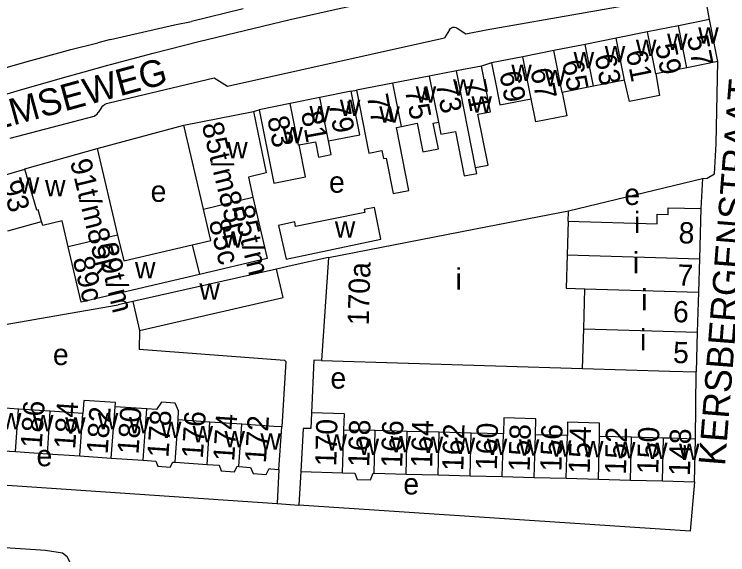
# Model space of a CAD drawing. Extents: x 159045 to 160918, y 380454 to 382516.
# Drawn here: x 159284.2 to 159418.5, y 381185.5 to 381287.1 of the extents above; entities that cross this region are included whole.
import ezdxf

# ---------------------------------------------------------------- set-up
doc = ezdxf.new("R2010")
doc.units = 0
for name, color, linetype in [('BLT_Basislijn', 7, 'Continuous'), ('BLT_Bebouwing', 7, 'Continuous'), ('BLT_Centroide', 7, 'Continuous'), ('BLT_Huisnummer', 7, 'Continuous'), ('BLT_Huisnummer_ tussenligend', 7, 'Continuous'), ('BLT_Huisnummer_reeks', 7, 'Continuous'), ('BLT_Onderverdeling_panden', 7, 'Continuous'), ('BLT_Straatnaam', 7, 'Continuous')]:
    doc.layers.add(name, color=color, linetype=linetype)

msp = doc.modelspace()

# ---------------------------------------------------------------- linework, layer by layer
at = {"layer": 'BLT_Basislijn'}
for p, q in [((159415.1, 381286.15), (159413.77, 381293.29)), ((159327.29, 381288.14), (159317.55, 381285.81)), ((159366.13, 381284.24), (159365.2, 381282.7)), ((159294.85, 381280.49), (159299.91, 381281.76)), ((159302.31, 381282.37), (159299.91, 381281.76)), ((159374.05, 381277.98), (159372.15, 381277.4)), ((159347.61, 381272.68), (159348.6, 381272.86)), ((159300.6, 381269.58), (159300.01, 381268.67)), ((159329.27, 381268.86), (159330.29, 381269.19)), ((159283.45, 381263.82), (159299.23, 381267.99)), ((159299.81, 381261.86), (159316.14, 381266.26)), ((159388.56, 381250.19), (159413.78, 381256.23)), ((159413.78, 381256.23), (159413.43, 381250.58)), ((159343.33, 381241.36), (159336.5, 381239.86)), ((159336.5, 381239.86), (159333.58, 381239.2)), ((159294.75, 381230.92), (159303.75, 381232.49)), ((159306.52, 381233.11), (159303.75, 381232.49)), ((159279.8, 381228.31), (159294.75, 381230.92)), ((159412.47, 381207.22), (159412.59, 381219.86)), ((159334.01, 381201.52), (159333.67, 381195.07)), ((159338.14, 381201.09), (159337.79, 381194.78)), ((159277.81, 381198.87), (159333.67, 381195.07)), ((159333.67, 381195.07), (159337.79, 381194.78))]:
    msp.add_line(p, q, dxfattribs=at)
for points in [[(159302.35, 381277.68), (159310.37, 381279.81), (159318.94, 381282), (159327.53, 381284.12), (159336.15, 381286.16), (159344.78, 381288.12), (159353.42, 381290), (159362.09, 381291.81), (159370.77, 381293.53), (159374.68, 381294.29)], [(159373.07, 381284.21), (159410.34, 381290.77), (159412.1, 381293.03), (159413.77, 381293.29)], [(159302.31, 381282.37), (159308.33, 381283.79), (159314.37, 381285.13), (159317.55, 381285.81)], [(159366.13, 381284.24), (159366.3, 381284.46), (159366.53, 381284.62), (159366.79, 381284.72), (159367.07, 381284.73), (159367.34, 381284.67), (159367.6, 381284.51)], [(159367.6, 381284.51), (159369.22, 381283.45), (159373.07, 381284.21)], [(159302.04, 381270.49), (159321.82, 381275.16), (159324.37, 381273.6), (159365.2, 381282.7)], [(159268.61, 381272.82), (159274.74, 381274.79), (159280.66, 381276.56), (159286.61, 381278.27), (159292.57, 381279.89), (159294.85, 381280.49)], [(159297.34, 381276.3), (159301.81, 381277.54), (159302.35, 381277.68)], [(159413.78, 381256.23), (159414.67, 381256.31), (159416, 381257.11), (159416.33, 381262.74), (159416.67, 381278.26)], [(159259.37, 381265.02), (159267.81, 381267.68), (159276.28, 381270.26), (159284.77, 381272.76), (159293.28, 381275.18), (159297.34, 381276.3)], [(159300.6, 381269.58), (159300.88, 381269.9), (159301.21, 381270.16), (159301.59, 381270.36), (159302.04, 381270.49)], [(159299.23, 381267.99), (159299.52, 381268.13), (159299.78, 381268.34), (159300.01, 381268.67)], [(159307.77, 381227.65), (159307.74, 381224.14), (159335.08, 381222.05)], [(159335.08, 381222.05), (159335.31, 381221.79), (159334.55, 381209.5)], [(159342.01, 381221.98), (159340.62, 381222.05), (159340.13, 381212.13)], [(159412.26, 381199.18), (159411.43, 381189.92), (159337.79, 381194.78)], [(159295.11, 381183.27), (159294.19, 381185.05), (159293.3, 381185.75), (159290.07, 381186.28), (159269.21, 381187.6)]]:
    msp.add_lwpolyline(points, dxfattribs=at)
at = {"layer": 'BLT_Bebouwing'}
for p, q in [((159415.1, 381286.15), (159409.24, 381284.98)), ((159416.67, 381278.26), (159415.1, 381286.15)), ((159409.24, 381284.98), (159403.38, 381283.82)), ((159403.38, 381283.82), (159397.51, 381282.65)), ((159397.51, 381282.65), (159391.65, 381281.48)), ((159385.78, 381280.32), (159379.92, 381279.15)), ((159391.65, 381281.48), (159385.78, 381280.32)), ((159379.92, 381279.15), (159374.05, 381277.98)), ((159367.43, 381276.5), (159362.33, 381275.52)), ((159372.15, 381277.4), (159367.43, 381276.5)), ((159410.81, 381277.09), (159404.95, 381275.93)), ((159362.33, 381275.52), (159355.46, 381274.2)), ((159355.46, 381274.2), (159348.6, 381272.86)), ((159393.22, 381273.6), (159387.35, 381272.43)), ((159399.08, 381274.76), (159393.22, 381273.6)), ((159347.61, 381272.68), (159341.75, 381271.5)), ((159341.75, 381271.5), (159336.16, 381270.38)), ((159330.29, 381269.19), (159333.05, 381255.38)), ((159356.15, 381265.86), (159357.09, 381266.04)), ((159299.81, 381261.86), (159303.65, 381245.61)), ((159280.19, 381256.28), (159286.19, 381257.99)), ((159413.43, 381250.58), (159413.18, 381241.16)), ((159343.33, 381241.36), (159342.01, 381221.98)), ((159413.18, 381241.16), (159413, 381234.84)), ((159333.58, 381239.2), (159306.52, 381233.11)), ((159413, 381234.84), (159412.79, 381227.35)), ((159306.52, 381233.11), (159307.77, 381227.65)), ((159412.79, 381227.35), (159412.59, 381219.86)), ((159342.01, 381221.98), (159391.19, 381220.49)), ((159309.15, 381212.9), (159303.21, 381213.3)), ((159290.99, 381212.45), (159284.98, 381212.86)), ((159297.11, 381212.04), (159290.99, 381212.45)), ((159321.04, 381210.42), (159315.03, 381210.82)), ((159327.05, 381210.01), (159321.04, 381210.42)), ((159352.14, 381208.84), (159346.24, 381208.92)), ((159358.18, 381208.67), (159352.14, 381208.84)), ((159364.21, 381208.51), (159358.18, 381208.67)), ((159370.24, 381208.35), (159364.21, 381208.51)), ((159376.28, 381208.19), (159370.24, 381208.35)), ((159388.34, 381207.87), (159382.31, 381208.03)), ((159400.41, 381207.55), (159394.38, 381207.71)), ((159406.44, 381207.39), (159400.41, 381207.55)), ((159412.26, 381199.18), (159412.47, 381207.22)), ((159278.43, 381205.27), (159284.44, 381204.86)), ((159284.44, 381204.86), (159290.45, 381204.46)), ((159290.45, 381204.46), (159296.57, 381204.05)), ((159296.57, 381204.05), (159302.47, 381203.65)), ((159302.47, 381203.65), (159308.48, 381203.24)), ((159314.49, 381202.84), (159320.5, 381202.43)), ((159338.14, 381201.09), (159346.02, 381200.89)), ((159351.93, 381200.8), (159357.96, 381200.64)), ((159357.96, 381200.64), (159363.99, 381200.47)), ((159363.99, 381200.47), (159370.03, 381200.31)), ((159370.03, 381200.31), (159376.06, 381200.15)), ((159376.06, 381200.15), (159382.09, 381199.99)), ((159382.09, 381199.99), (159388.13, 381199.83)), ((159388.13, 381199.83), (159394.16, 381199.67)), ((159394.16, 381199.67), (159400.19, 381199.51)), ((159400.19, 381199.51), (159406.23, 381199.35)), ((159406.23, 381199.35), (159412.26, 381199.18))]:
    msp.add_line(p, q, dxfattribs=at)
for points in [[(159374.05, 381277.98), (159375.03, 381273.08), (159375.62, 381270.1), (159381.49, 381271.26)], [(159416.67, 381278.26), (159411.77, 381277.28), (159410.81, 381277.09)], [(159371.06, 381258.29), (159373.41, 381258.76), (159371.5, 381268.34), (159373.86, 381268.81), (159372.15, 381277.4)], [(159404.95, 381275.93), (159405.64, 381271.87), (159400.01, 381270.76), (159399.08, 381274.76)], [(159343.38, 381263.32), (159349.24, 381264.48), (159347.61, 381272.68)], [(159348.6, 381272.86), (159350.95, 381261.03), (159353.39, 381261.51), (159353.69, 381259.98), (159354.22, 381260.08), (159355.54, 381253.42), (159358.46, 381254), (159356.15, 381265.86)], [(159387.35, 381272.43), (159388.23, 381268.06), (159382.4, 381266.91), (159381.49, 381271.26)], [(159336.16, 381270.38), (159330.29, 381269.19)], [(159316.14, 381266.26), (159329.27, 381268.86)], [(159329.27, 381268.86), (159331.64, 381257.28), (159328.27, 381256.48), (159329.14, 381252.74)], [(159357.09, 381266.04), (159360.04, 381266.63), (159361.11, 381261.23), (159364.04, 381261.82), (159363.08, 381266.66), (159364.06, 381266.86)], [(159364.06, 381266.86), (159364.51, 381264.56), (159367.25, 381265.11), (159368.92, 381256.74), (159371.28, 381257.21), (159371.06, 381258.29)], [(159319.84, 381250.49), (159316.14, 381266.26)], [(159337.84, 381262.56), (159340.92, 381263.17), (159341.5, 381260.26), (159343.89, 381260.74), (159343.38, 381263.32)], [(159286.19, 381257.99), (159286.17, 381258.05), (159299.81, 381261.86)], [(159333.05, 381255.38), (159339.06, 381256.58), (159337.84, 381262.56)], [(159329.14, 381252.74), (159331.84, 381241.18), (159319.07, 381238.18)], [(159388.49, 381248.22), (159405.21, 381247.73), (159405.26, 381249.56), (159407.29, 381249.5), (159407.33, 381250.75), (159413.43, 381250.58)], [(159317.7, 381243.76), (159321.22, 381244.59), (159319.84, 381250.49)], [(159343.33, 381241.36), (159373.27, 381247.2), (159388.56, 381250.19)], [(159388.49, 381248.22), (159388.55, 381250), (159388.56, 381250.19)], [(159283.01, 381246.38), (159289.35, 381248.18)], [(159294.36, 381243.36), (159293.21, 381248.25), (159289.58, 381247.4), (159289.35, 381248.18)], [(159303.65, 381245.61), (159304.8, 381240.73), (159317.7, 381243.76)], [(159319.07, 381238.18), (159296.81, 381232.95), (159294.36, 381243.36)], [(159307.77, 381227.65), (159334.8, 381233.87), (159333.58, 381239.2)], [(159391.19, 381220.49), (159407.59, 381220), (159412.59, 381219.86)], [(159284.98, 381212.86), (159281.62, 381213.08), (159281.84, 381216.43), (159279.2, 381216.6)], [(159303.21, 381213.3), (159303.26, 381214.09), (159297.29, 381214.5), (159297.11, 381212.04)], [(159315.03, 381210.82), (159315.12, 381212.5), (159314.49, 381214), (159311.92, 381214.17), (159311, 381212.78), (159309.15, 381212.9)], [(159340.13, 381212.13), (159340.05, 381209.18), (159338.59, 381209.22), (159338.14, 381201.09)], [(159346.24, 381208.92), (159346.36, 381211.97), (159340.13, 381212.13)], [(159382.31, 381208.03), (159382.37, 381211.03), (159376.36, 381211.19), (159376.28, 381208.19)], [(159333.05, 381209.61), (159327.05, 381210.01)], [(159334.55, 381209.5), (159333.05, 381209.61)], [(159334.01, 381201.52), (159334.55, 381209.5)], [(159394.38, 381207.71), (159394.37, 381210.22), (159388.36, 381210.38), (159388.34, 381207.87)], [(159412.47, 381207.22), (159407.48, 381207.36), (159406.44, 381207.39)], [(159308.48, 381203.24), (159310.86, 381203.08), (159311.22, 381202.1), (159313.55, 381201.94), (159314.03, 381202.87), (159314.49, 381202.84)], [(159320.5, 381202.43), (159322.8, 381202.31), (159323.18, 381201.21), (159325.65, 381201.04), (159326.18, 381202.09), (159326.51, 381202.03)], [(159326.51, 381202.03), (159328.66, 381201.89), (159329.15, 381200.75), (159331.61, 381200.58), (159332.2, 381201.67), (159332.51, 381201.62)], [(159332.51, 381201.62), (159334.01, 381201.52)], [(159346.02, 381200.89), (159348.33, 381200.83), (159348.77, 381199.6), (159351.26, 381199.52), (159351.78, 381200.82), (159351.93, 381200.8)]]:
    msp.add_lwpolyline(points, dxfattribs=at)
msp.add_lwpolyline([(159350.06, 381250.42), (159350.19, 381249.87), (159337.17, 381247.2), (159336.99, 381248.07), (159333.93, 381247.39), (159335.39, 381241.06), (159353.21, 381244.85), (159351.99, 381250.79)], close=True, dxfattribs=at)
at = {"layer": 'BLT_Onderverdeling_panden'}
for p, q in [((159410.81, 381277.09), (159409.24, 381284.98)), ((159404.95, 381275.93), (159403.38, 381283.82)), ((159399.08, 381274.76), (159397.51, 381282.65)), ((159387.35, 381272.43), (159385.78, 381280.32)), ((159393.22, 381273.6), (159391.65, 381281.48)), ((159381.49, 381271.26), (159379.92, 381279.15)), ((159371.06, 381258.29), (159367.43, 381276.5)), ((159357.09, 381266.04), (159355.46, 381274.2)), ((159343.38, 381263.32), (159341.75, 381271.5)), ((159288.46, 381250.26), (159286.19, 381257.99)), ((159319.84, 381250.49), (159329.14, 381252.74)), ((159388.49, 381248.22), (159388.31, 381241.9)), ((159303.65, 381245.61), (159294.36, 381243.36)), ((159317.7, 381243.76), (159319.07, 381238.18)), ((159388.31, 381241.9), (159413.18, 381241.16)), ((159391.41, 381227.98), (159391.64, 381235.47)), ((159391.64, 381235.47), (159413, 381234.84)), ((159391.19, 381220.49), (159391.41, 381227.98)), ((159391.41, 381227.98), (159412.79, 381227.35)), ((159302.47, 381203.65), (159303.21, 381213.3)), ((159284.44, 381204.86), (159284.98, 381212.86)), ((159290.45, 381204.46), (159290.99, 381212.45)), ((159296.57, 381204.05), (159297.11, 381212.04)), ((159308.48, 381203.24), (159309.15, 381212.9)), ((159314.49, 381202.84), (159315.03, 381210.82)), ((159320.5, 381202.43), (159321.04, 381210.42)), ((159326.51, 381202.03), (159327.05, 381210.01)), ((159346.02, 381200.89), (159346.24, 381208.92)), ((159351.93, 381200.8), (159352.14, 381208.84)), ((159357.96, 381200.64), (159358.18, 381208.67)), ((159363.99, 381200.47), (159364.21, 381208.51)), ((159370.03, 381200.31), (159370.24, 381208.35)), ((159376.06, 381200.15), (159376.28, 381208.19)), ((159382.09, 381199.99), (159382.31, 381208.03)), ((159388.13, 381199.83), (159388.34, 381207.87)), ((159394.16, 381199.67), (159394.38, 381207.71)), ((159400.19, 381199.51), (159400.41, 381207.55)), ((159406.23, 381199.35), (159406.44, 381207.39))]:
    msp.add_line(p, q, dxfattribs=at)
for points in [[(159362.33, 381275.52), (159364.06, 381266.86)], [(159337.84, 381262.56), (159337.72, 381262.53), (159336.16, 381270.38)], [(159289.35, 381248.18), (159288.73, 381250.33), (159288.46, 381250.26)], [(159388.31, 381241.9), (159388.12, 381235.58), (159391.64, 381235.47)]]:
    msp.add_lwpolyline(points, dxfattribs=at)

# ---------------------------------------------------------------- texts
at = {"layer": 'BLT_Centroide'}
for s, p in [('w', (159412.95, 381281.62)), ('w', (159407.09, 381280.45)), ('w', (159401.23, 381279.28)), ('w', (159395.36, 381278.12)), ('w', (159389.5, 381276.95)), ('w', (159377.77, 381274.62)), ('w', (159384.08, 381273.61)), ('w', (159366.8, 381271.86)), ('w', (159359.77, 381270.52)), ('w', (159345.5, 381268)), ('w', (159370.26, 381268.65)), ('w', (159339.77, 381266.84)), ('w', (159352.91, 381266.75)), ('w', (159334.67, 381262.89)), ('w', (159324.29, 381260.05)), ('w', (159285.06, 381253.41)), ('e', (159343.45, 381253.57)), ('w', (159290, 381252.9)), ('e', (159309.87, 381251.85)), ('e', (159399.05, 381251.26)), ('i', (159400.87, 381245.97)), ('w', (159344.55, 381245.14)), ('w', (159323.46, 381243.26)), ('i', (159400.65, 381238.38)), ('w', (159306.93, 381237.44)), ('i', (159367.27, 381235.34)), ('w', (159319.05, 381233.44)), ('i', (159402.21, 381231.41)), ('i', (159402, 381223.91)), ('e', (159291.48, 381221.14)), ('e', (159343.72, 381216.71)), ('w', (159281.7, 381209.06)), ('w', (159299.92, 381209.06)), ('w', (159287.72, 381208.66)), ('w', (159293.78, 381208.25)), ('w', (159305.81, 381208.28)), ('w', (159311.8, 381207.39)), ('w', (159317.77, 381206.62)), ('w', (159323.77, 381205.69)), ('w', (159330.53, 381205.22)), ('w', (159342.98, 381205.06)), ('w', (159355.05, 381204.73)), ('w', (159349.02, 381204.25)), ('w', (159361.09, 381204.58)), ('w', (159367.12, 381204.42)), ('w', (159373.16, 381204.25)), ('w', (159379.19, 381204.09)), ('w', (159385.22, 381203.92)), ('w', (159391.25, 381203.77)), ('w', (159397.28, 381203.61)), ('w', (159403.31, 381203.45)), ('e', (159288.39, 381202.1)), ('w', (159409.34, 381203.28)), ('e', (159357.44, 381196.79))]:
    msp.add_text(s, height=4, dxfattribs=at).set_placement(p)
at = {"layer": 'BLT_Huisnummer'}
for s, rotation, p in [('57', 281.2429, (159410.8, 381282.86)), ('61', 281.2429, (159399.3, 381280.06)), ('65', 281.2429, (159387.3, 381278.21)), ('69', 281.2443, (159375.49, 381276.12)), ('73', 281.2471, (159363.51, 381274.07)), ('77', 280.3517, (159350.55, 381271.82)), ('83', 281.3539, (159331.8, 381267.64)), ('93', 285.7821, (159281.77, 381255.31)), ('8', 358.3956, (159409.22, 381244.07)), ('170a', 88.3027, (159350.93, 381228.55)), ('7', 358.3071, (159408.99, 381236.09)), ('6', 358.3029, (159408.16, 381229.23)), ('5', 358.3058, (159408.17, 381221.54)), ('184', 86.1398, (159295.66, 381205.25)), ('180', 86.1388, (159307.58, 381204.27)), ('176', 86.1373, (159319.69, 381203.46)), ('172', 86.1471, (159331.57, 381202.62)), ('170', 88.468, (159344.82, 381202.04)), ('164', 88.4678, (159362.87, 381201.8)), ('160', 88.4678, (159375.05, 381201.33)), ('156', 88.4678, (159387.2, 381201.08)), ('152', 88.4678, (159399.35, 381200.5)), ('148', 88.4678, (159411.4, 381200.25))]:
    msp.add_text(s, height=4, rotation=rotation, dxfattribs=at).set_placement(p)
at = {"layer": 'BLT_Huisnummer_ tussenligend'}
for s, rotation, p in [('59', 281.2429, (159404.83, 381281.32)), ('63', 281.2429, (159393.42, 381279.31)), ('67', 281.2429, (159381.33, 381276.69)), ('71', 281.2443, (159368.93, 381274.48)), ('75', 281.2471, (159357.71, 381272.88)), ('79', 280.3517, (159343.32, 381270.37)), ('81', 280.3517, (159338.18, 381268.63)), ('186', 86.1398, (159289.36, 381205.42)), ('182', 86.1388, (159301.78, 381204.29)), ('178', 86.1373, (159313.21, 381203.64)), ('174', 86.1471, (159325.6, 381202.95)), ('168', 88.468, (159351.03, 381201.93)), ('166', 88.4678, (159357.24, 381201.8)), ('162', 88.4678, (159368.74, 381201.17)), ('158', 88.4678, (159381.23, 381201.08)), ('154', 88.4678, (159392.53, 381200.66)), ('150', 88.4678, (159405.43, 381200.58))]:
    msp.add_text(s, height=4, rotation=rotation, dxfattribs=at).set_placement(p)
at = {"layer": 'BLT_Huisnummer_reeks'}
for s, p in [('85t/m85j', (159319.46, 381266.36)), ('91t/m85k', (159294.67, 381259.45)), ('85t/m', (159325.3, 381250.72)), ('85c', (159320.79, 381248.12)), ('89t/m', (159299.66, 381243.67)), ('89c', (159295.15, 381241.07))]:
    msp.add_text(s, height=4, rotation=283.7694, dxfattribs=at).set_placement(p)
at = {"layer": 'BLT_Straatnaam'}
for s, rotation, p in [('BLAARTHEMSEWEG', 15.2914, (159249.96, 381256.9)), ('KERSBERGENSTRAAT', 85.4772, (159417.99, 381202.09))]:
    msp.add_text(s, height=5, rotation=rotation, dxfattribs=at).set_placement(p)

doc.saveas('drawing.dxf')
